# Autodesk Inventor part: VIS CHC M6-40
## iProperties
Created: 2004-11
Part Number: VIS CHC M6-40
Document SubType Name: Modeling
Designer: Bruno
Manufacturer: Standard
Standards Organization: Custom
Author: Bruno
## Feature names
1. Base1
